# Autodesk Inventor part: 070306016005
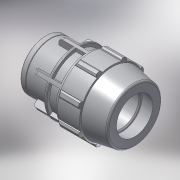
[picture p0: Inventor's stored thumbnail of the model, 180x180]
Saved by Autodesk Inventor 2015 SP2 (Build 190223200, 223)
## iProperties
Created: 2017-02
Part Number: 070306016005
Material: PVC-Piping
Description: PLASSON FEMALE ADAPTOR 16-1/2"
Document SubType Name: Modeling
Designer: KIM
Mass: 92.6774 g
Surface Area: 199.44 cm^2
Volume: 66.1981 cm^3
Density: 1.4 g/cm^3
Appearance: Smooth - White
Author: KIM
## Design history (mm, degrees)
derived "07030.ipt"
feature "Solid1::07030.ipt"
tag "TaggingFeature1"
body "Solid1"
other parameters: "d2" = 16, "d4" = 10.42857, "d5" = 18.25, "d7" = 39, "d9" = 10.42857, "d11" = 2.08571, "d12" = 31.2, "d13" = 120 deg, "d14" = 24, "d15" = 12 deg, "d16" = 35.1, "d18" = 0.8, "d19" = 35 deg, "d20" = 17.5 deg, "d21" = 36.27, "d23" = 0, "d25" = 360 deg, "d27" = 0.78, "d34" = 1.95, "d35" = 21.9, "d36" = 0, "d42" = 18.25, "d43" = 1.17, "d46" = 0.48, "d49" = 52, "d51" = 73, "d53" = 0.32, "d55" = 360 deg, "d61" = 19, "d62" = 12.8, "d63" = 18.631, "d64" = 24.33333, "d65" = 1.95, "d66" = 0.5, "d67" = 1, "d68" = 5.7, "d69" = 28.08, "d70" = 0.975, "d_" = 16, "E_" = 39, "H_" = 73, "l_" = 52, "l_2" = 19, "Rp_" = 18.631
